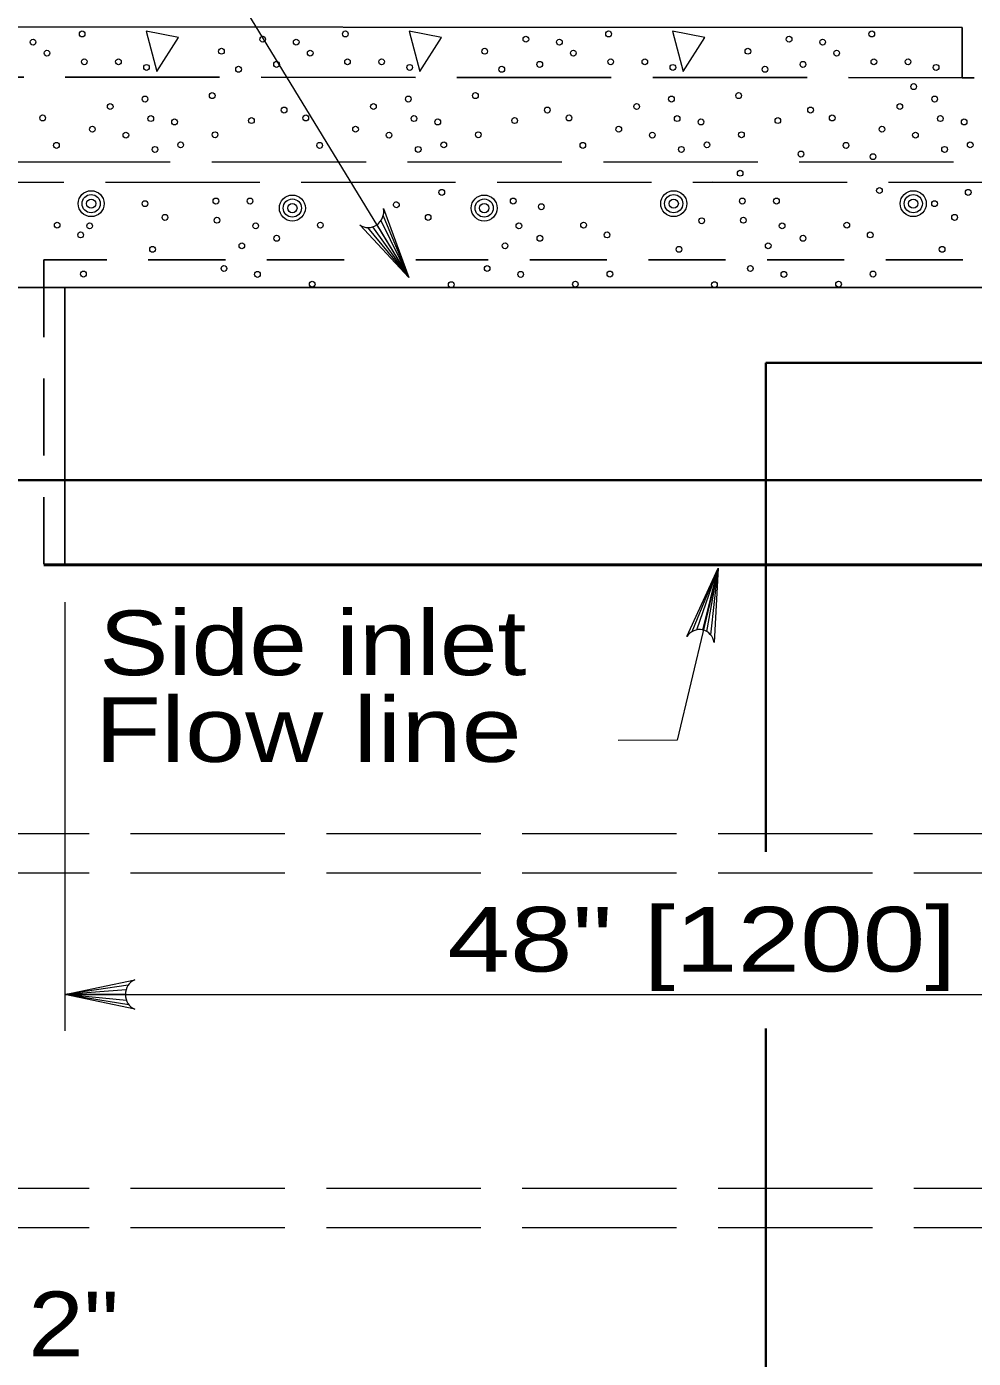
# Model space of a CAD drawing. Extents: x 1329.9 to 1363.9, y 715.5 to 737.5.
# Drawn here: x 1341.364 to 1343.646, y 730.9 to 734.111 of the extents above; entities that cross this region are included whole.
import ezdxf
from ezdxf.enums import TextEntityAlignment as Align

# ---------------------------------------------------------------- set-up
doc = ezdxf.new("R2010")
doc.units = 0
doc.header["$LTSCALE"] = 0.062
doc.linetypes.add('LONG_DASHED', pattern=[7.5, 6, -1.5])
doc.linetypes.add('MEDIUM_DASHED', pattern=[4.5, 3, -1.5])
doc.layers.add('1', color=7, linetype='Continuous', lineweight=13)

msp = doc.modelspace()

# ---------------------------------------------------------------- linework, layer by layer
at = {"layer": '1'}
for p, q in [((1341.73025, 734.08492), (1341.65233, 734.10017)), ((1342.28683, 734.10017), (1342.31242, 734.00275)), ((1342.36467, 734.08492), (1342.28683, 734.10017)), ((1342.92117, 734.10017), (1342.94683, 734.00275)), ((1342.31242, 734.00275), (1342.36467, 734.08492)), ((1343.0165, 733.73575), (1343.01725, 733.7365)), ((1343.0165, 733.73575), (1343.01725, 733.7365)), ((1343.0165, 733.73575), (1343.01725, 733.7365)), ((1343.0165, 733.73575), (1343.01725, 733.7365)), ((1343.0165, 733.73575), (1343.01725, 733.7365)), ((1343.0165, 733.73575), (1343.01725, 733.7365)), ((1343.0165, 733.73575), (1343.01725, 733.7365)), ((1343.0165, 733.73575), (1343.01725, 733.7365)), ((1343.0165, 733.73575), (1343.01725, 733.7365)), ((1343.0165, 733.73575), (1343.01725, 733.7365)), ((1343.0165, 733.73575), (1343.01725, 733.7365)), ((1343.0165, 733.73575), (1343.01725, 733.7365)), ((1343.0165, 733.73575), (1343.01725, 733.7365)), ((1343.0165, 733.73575), (1343.01725, 733.7365)), ((1343.0165, 733.73575), (1343.01725, 733.7365)), ((1343.0165, 733.73575), (1343.01725, 733.7365)), ((1343.0165, 733.73575), (1343.01725, 733.7365)), ((1342.22375, 733.6545), (1342.28558, 733.50625)), ((1342.18633, 733.6265), (1342.28558, 733.50625)), ((1342.19808, 733.62817), (1342.28558, 733.50625)), ((1342.20817, 733.63317), (1342.28558, 733.50625)), ((1342.21842, 733.6435), (1342.28558, 733.50625)), ((1341.406, 732.81183), (1341.45675, 732.81183)), ((1342.96883, 732.65267), (1343.03117, 732.8055)), ((1342.98, 732.6565), (1343.03117, 732.8055)), ((1342.994, 732.65617), (1343.03117, 732.8055)), ((1343.00417, 732.65242), (1343.03117, 732.8055)), ((1343.01325, 732.64475), (1343.03117, 732.8055)), ((1341.45675, 732.72325), (1341.45675, 731.69)), ((1341.60908, 731.79992), (1341.45675, 731.77733)), ((1341.60908, 731.79992), (1341.45675, 731.77733)), ((1341.60392, 731.78875), (1341.45675, 731.77733)), ((1341.60392, 731.78875), (1341.45675, 731.77733)), ((1341.45675, 731.77733), (1345.1775, 731.77733)), ((1341.60233, 731.77733), (1341.45675, 731.77733)), ((1341.60508, 731.76292), (1341.45675, 731.77733)), ((1341.61092, 731.75242), (1341.45675, 731.77733)), ((1341.60233, 731.77733), (1341.45675, 731.77733)), ((1341.60508, 731.76292), (1341.45675, 731.77733)), ((1341.61092, 731.75242), (1341.45675, 731.77733))]:
    msp.add_line(p, q, dxfattribs=at)
at = {"layer": '1', "lineweight": 25}
for p, q in [((1343.61975, 734.10892), (1343.61975, 733.988)), ((1343.64817, 733.988), (1343.61975, 733.988)), ((1341.09175, 733.48175), (1343.775, 733.48175)), ((1341.45675, 733.48175), (1341.45675, 732.81183)), ((1341.406, 732.81483), (1345.24542, 732.81483)), ((1341.45675, 732.81183), (1345.1775, 732.81183))]:
    msp.add_line(p, q, dxfattribs=at)
at = {"layer": '1', "linetype": 'LONG_DASHED', "lineweight": 25}
msp.add_line((1340.51358, 733.98983), (1343.61975, 733.988), dxfattribs=at)
at = {"layer": '1', "linetype": 'LONG_DASHED'}
for p, q in [((1344.5425, 733.7845), (1340.61017, 733.7845)), ((1340.61017, 733.73575), (1344.5425, 733.73575)), ((1340.67083, 732.1655), (1345.98667, 732.1655)), ((1340.67083, 732.07058), (1345.98667, 732.07058)), ((1340.67083, 731.31067), (1345.98667, 731.31067)), ((1340.67083, 731.21567), (1345.98667, 731.21567))]:
    msp.add_line(p, q, dxfattribs=at)
at = {"layer": '1', "linetype": 'MEDIUM_DASHED', "lineweight": 25}
for p, q in [((1341.406, 733.54867), (1341.406, 732.81483)), ((1342.12942, 733.54867), (1341.406, 733.54867)), ((1344.76517, 733.54867), (1342.30275, 733.54867))]:
    msp.add_line(p, q, dxfattribs=at)
at = {"layer": '1', "lineweight": 35}
for p, q in [((1343.146, 733.30067), (1344.65908, 733.30067)), ((1343.146, 733.30067), (1343.146, 732.12117)), ((1343.146, 731.695), (1343.146, 730.17492))]:
    msp.add_line(p, q, dxfattribs=at)
at = {"layer": '1'}
for points in [[(1341.074, 735.0185), (1341.36325, 735.0185), (1342.28558, 733.50625)], [(1341.65233, 734.10017), (1341.678, 734.00275), (1341.73025, 734.08492)], [(1342.94683, 734.00275), (1342.999, 734.08492), (1342.92117, 734.10017)], [(1342.22492, 733.67275), (1342.28558, 733.50625), (1342.16725, 733.63317)], [(1343.03117, 732.8055), (1342.93225, 732.39092), (1342.79033, 732.39017)], [(1342.95533, 732.64033), (1343.03117, 732.8055), (1343.02125, 732.62592)], [(1341.625, 731.74175), (1341.45675, 731.77733), (1341.625, 731.813)], [(1341.625, 731.74175), (1341.45675, 731.77733), (1341.625, 731.813)]]:
    msp.add_lwpolyline(points, dxfattribs=at)
at = {"layer": '1', "lineweight": 25}
msp.add_lwpolyline([(1343.61975, 734.10892), (1340.63383, 734.1105), (1340.51358, 733.98983)], dxfattribs=at)
at = {"layer": '1', "lineweight": 35}
msp.add_lwpolyline([(1340.12008, 733.01742), (1346.51367, 733.01742), (1346.51367, 732.60617)], dxfattribs=at)
at = {"layer": '1'}
for centre, radius in [((1341.5199, 733.68422), 0.03133), ((1342.92403, 733.68422), 0.03133), ((1343.50151, 733.68422), 0.03133), ((1341.5199, 733.68422), 0.0219), ((1341.5199, 733.68422), 0.01122), ((1342.00487, 733.67364), 0.03133), ((1342.00487, 733.67364), 0.0219), ((1342.00487, 733.67364), 0.01122), ((1342.46727, 733.67364), 0.03133), ((1342.46727, 733.67364), 0.0219), ((1342.46727, 733.67364), 0.01122), ((1342.92403, 733.68422), 0.0219), ((1342.92403, 733.68422), 0.01122), ((1343.50151, 733.68422), 0.0219), ((1343.50151, 733.68422), 0.01122)]:
    msp.add_circle(centre, radius, dxfattribs=at)
for centre, major_axis in [((1341.49828, 734.09343), (0, 0.00718)), ((1342.13268, 734.09343), (0, 0.00718)), ((1342.76708, 734.09343), (0, 0.00718)), ((1343.40148, 734.09343), (0, 0.00718)), ((1341.37981, 734.07378), (0, 0.00718)), ((1341.93337, 734.08078), (0, 0.00718)), ((1342.01421, 734.07378), (0, 0.00718)), ((1342.56777, 734.08078), (0, 0.00718)), ((1342.6486, 734.07378), (0, 0.00718)), ((1343.20217, 734.08078), (0, 0.00718)), ((1343.283, 734.07378), (0, 0.00718)), ((1341.41348, 734.0472), (0, 0.00718)), ((1341.50341, 734.02632), (0, 0.00718)), ((1341.58567, 734.02632), (0, 0.00718)), ((1341.83404, 734.05173), (0, 0.00718)), ((1342.04788, 734.0472), (0, 0.00718)), ((1342.13781, 734.02632), (0, 0.00718)), ((1342.22007, 734.02632), (0, 0.00718)), ((1342.46844, 734.05173), (0, 0.00718)), ((1342.68228, 734.0472), (0, 0.00718)), ((1342.77221, 734.02632), (0, 0.00718)), ((1342.85447, 734.02632), (0, 0.00718)), ((1343.10283, 734.05173), (0, 0.00718)), ((1343.31668, 734.0472), (0, 0.00718)), ((1343.40661, 734.02632), (0, 0.00718)), ((1343.48887, 734.02632), (0, 0.00718)), ((1341.65329, 734.01272), (0, 0.00718)), ((1341.87517, 734.00819), (0, 0.00718)), ((1341.96678, 734.02), (0, 0.00718)), ((1342.28768, 734.01272), (0, 0.00718)), ((1342.50957, 734.00819), (0, 0.00718)), ((1342.60118, 734.02), (0, 0.00718)), ((1342.92208, 734.01272), (0, 0.00718)), ((1343.14396, 734.00819), (0, 0.00718)), ((1343.23558, 734.02), (0, 0.00718)), ((1343.55648, 734.01272), (0, 0.00718)), ((1343.50256, 733.96649), (0, 0.00718)), ((1341.64985, 733.93654), (0, 0.00718)), ((1341.81173, 733.94472), (0, 0.00718)), ((1342.28425, 733.93654), (0, 0.00718)), ((1342.44613, 733.94472), (0, 0.00718)), ((1342.91865, 733.93654), (0, 0.00718)), ((1343.08052, 733.94472), (0, 0.00718)), ((1343.55305, 733.93654), (0, 0.00718)), ((1341.5659, 733.91841), (0, 0.00718)), ((1341.98508, 733.90996), (0, 0.00718)), ((1342.2003, 733.91841), (0, 0.00718)), ((1342.61948, 733.90996), (0, 0.00718)), ((1342.8347, 733.91841), (0, 0.00718)), ((1343.25387, 733.90996), (0, 0.00718)), ((1343.46909, 733.91841), (0, 0.00718)), ((1341.40291, 733.89093), (0, 0.00718)), ((1341.52281, 733.86373), (0, 0.00718)), ((1341.6636, 733.88942), (0, 0.00718)), ((1341.72096, 733.88119), (0, 0.00718)), ((1341.90625, 733.8846), (0, 0.00718)), ((1342.03731, 733.89093), (0, 0.00718)), ((1342.15721, 733.86373), (0, 0.00718)), ((1342.29799, 733.88942), (0, 0.00718)), ((1342.35535, 733.88119), (0, 0.00718)), ((1342.54065, 733.8846), (0, 0.00718)), ((1342.67171, 733.89093), (0, 0.00718)), ((1342.79161, 733.86373), (0, 0.00718)), ((1342.93239, 733.88942), (0, 0.00718)), ((1342.98975, 733.88119), (0, 0.00718)), ((1343.17505, 733.8846), (0, 0.00718)), ((1343.30611, 733.89093), (0, 0.00718)), ((1343.42601, 733.86373), (0, 0.00718)), ((1343.56679, 733.88942), (0, 0.00718)), ((1343.62415, 733.88119), (0, 0.00718)), ((1341.60359, 733.84951), (0, 0.00718)), ((1341.8186, 733.85035), (0, 0.00718)), ((1342.23799, 733.84951), (0, 0.00718)), ((1342.453, 733.85035), (0, 0.00718)), ((1342.87239, 733.84951), (0, 0.00718)), ((1343.0874, 733.85035), (0, 0.00718)), ((1343.50679, 733.84951), (0, 0.00718)), ((1341.43627, 733.82471), (0, 0.00718)), ((1341.6738, 733.81503), (0, 0.00718)), ((1341.73549, 733.82595), (0, 0.00718)), ((1342.07067, 733.82471), (0, 0.00718)), ((1342.3082, 733.81503), (0, 0.00718)), ((1342.36989, 733.82595), (0, 0.00718)), ((1342.70507, 733.82471), (0, 0.00718)), ((1342.9426, 733.81503), (0, 0.00718)), ((1343.00429, 733.82595), (0, 0.00718)), ((1343.23072, 733.80384), (0, 0.00718)), ((1343.33947, 733.82471), (0, 0.00718)), ((1343.57699, 733.81503), (0, 0.00718)), ((1343.63869, 733.82595), (0, 0.00718)), ((1343.4046, 733.79751), (0, 0.00718)), ((1343.08428, 733.75761), (0, 0.00718)), ((1342.36508, 733.71137), (0, 0.00718)), ((1343.42003, 733.71591), (0, 0.00718)), ((1343.63388, 733.71137), (0, 0.00718)), ((1341.64959, 733.68417), (0, 0.00718)), ((1341.82061, 733.6905), (0, 0.00718)), ((1341.90287, 733.6905), (0, 0.00718)), ((1342.25545, 733.68162), (-0.00115, 0.00709)), ((1342.53727, 733.6905), (0, 0.00718)), ((1342.60488, 733.6769), (0, 0.00718)), ((1343.08941, 733.6905), (0, 0.00718)), ((1343.17167, 733.6905), (0, 0.00718)), ((1343.55278, 733.68417), (0, 0.00718)), ((1341.69785, 733.65121), (0, 0.00718)), ((1341.82315, 733.64427), (0, 0.00718)), ((1342.33225, 733.65121), (0, 0.00718)), ((1342.99158, 733.64304), (0, 0.00718)), ((1343.09194, 733.64427), (0, 0.00718)), ((1343.60105, 733.65121), (0, 0.00718)), ((1341.43801, 733.63246), (0, 0.00718)), ((1341.49453, 733.60889), (0, 0.00718)), ((1341.51618, 733.63067), (0, 0.00718)), ((1341.91656, 733.63067), (0, 0.00718)), ((1342.07241, 733.63246), (0, 0.00718)), ((1342.55096, 733.63067), (0, 0.00718)), ((1342.70681, 733.63246), (0, 0.00718)), ((1342.76333, 733.60889), (0, 0.00718)), ((1343.18536, 733.63067), (0, 0.00718)), ((1343.34121, 733.63246), (0, 0.00718)), ((1343.39772, 733.60889), (0, 0.00718)), ((1341.8831, 733.58259), (0, 0.00718)), ((1341.96705, 733.60072), (0, 0.00718)), ((1342.5175, 733.58259), (0, 0.00718)), ((1342.60145, 733.60072), (0, 0.00718)), ((1343.15189, 733.58259), (0, 0.00718)), ((1343.23585, 733.60072), (0, 0.00718)), ((1341.66788, 733.57414), (0, 0.00718)), ((1342.93667, 733.57414), (0, 0.00718)), ((1343.57107, 733.57414), (0, 0.00718)), ((1341.5014, 733.51453), (0, 0.00718)), ((1341.84001, 733.5279), (0, 0.00718)), ((1341.92079, 733.51369), (0, 0.00718)), ((1342.47441, 733.5279), (0, 0.00718)), ((1342.55519, 733.51369), (0, 0.00718)), ((1342.7702, 733.51453), (0, 0.00718)), ((1343.10881, 733.5279), (0, 0.00718)), ((1343.18959, 733.51369), (0, 0.00718)), ((1343.4046, 733.51453), (0, 0.00718)), ((1342.05269, 733.49012), (0, 0.00718)), ((1342.38787, 733.48889), (0, 0.00718)), ((1342.68709, 733.49012), (0, 0.00718)), ((1343.02227, 733.48889), (0, 0.00718)), ((1343.32149, 733.49012), (0, 0.00718))]:
    msp.add_ellipse(centre, major_axis=major_axis, ratio=0.944544, dxfattribs=at)
for centre, major_axis, start_param, end_param in [((1342.18886, 733.66481), (-0.0135, -0.03599), 6.0318625, 8.4024756), ((1342.98479, 732.61919), (0.01735, 0.0343), 5.3349122, 7.7055254), ((1341.63866, 731.77737), (0, 0.03844), 0.3855052, 2.7561184), ((1341.63866, 731.77737), (0, 0.03844), 0.3855052, 2.7561184)]:
    msp.add_ellipse(centre, major_axis=major_axis, ratio=0.944544, start_param=start_param, end_param=end_param, dxfattribs=at)

# ---------------------------------------------------------------- texts
for s, width, p in [('Side inlet', 1.2, (1341.53925, 732.54733)), ('Flow line', 1.25, (1341.52883, 732.33825)), ('48" [1200] min.', 1.3, (1342.3785, 731.83267))]:
    msp.add_text(s, height=0.156, dxfattribs=dict(at, width=width)).set_placement(p)
at = {"layer": '1', "width": 1.15}
msp.add_text('2"', height=0.156, dxfattribs=at).set_placement((1341.47771, 730.905), align=Align.CENTER)

doc.saveas('drawing.dxf')
